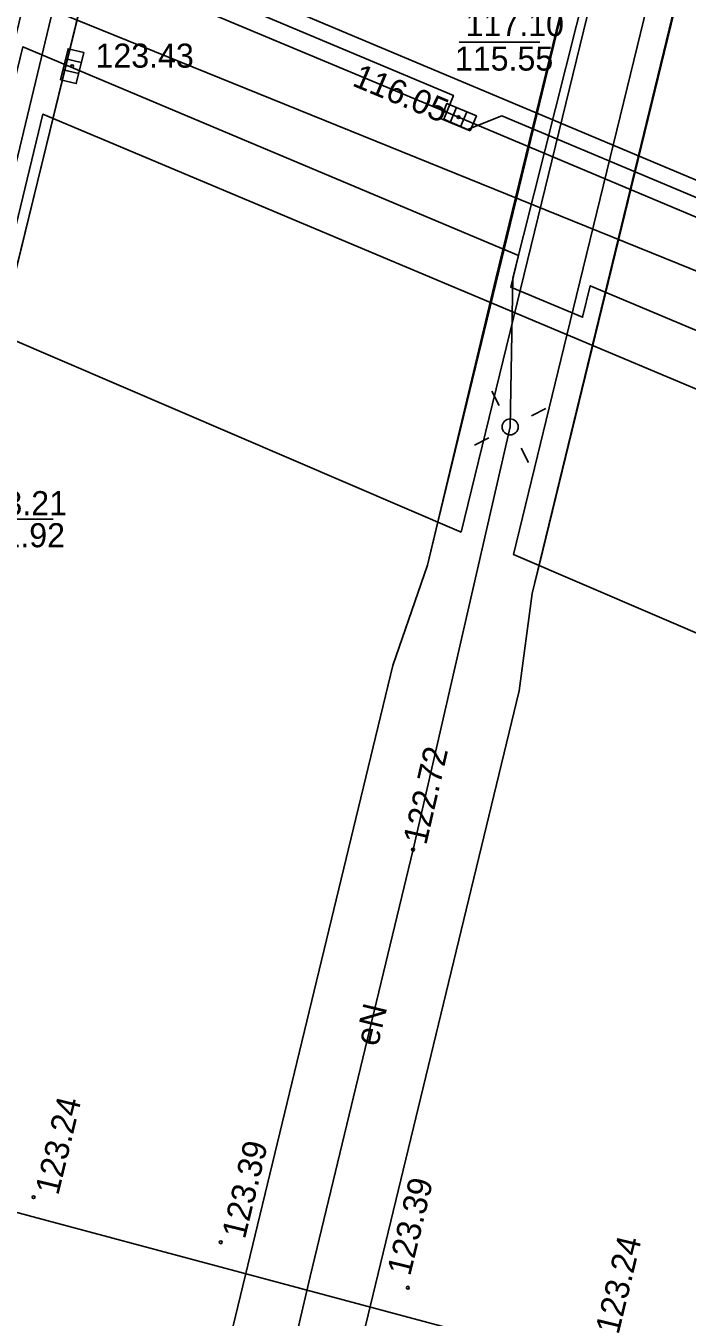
# Model space of a CAD drawing. Extents: x 6424617 to 6425697, y 5665845 to 5667190.
# Drawn here: x 6425440.97 to 6425461.6, y 5666910.57 to 5666950.84 of the extents above; entities that cross this region are included whole.
import ezdxf

# ---------------------------------------------------------------- set-up
doc = ezdxf.new("R2010")
doc.units = 0
for name, color, linetype in [('Warstwa 1', 7, 'Continuous'), ('Warstwa 12', 7, 'Continuous'), ('Warstwa 13', 7, 'Continuous'), ('Warstwa 14', 7, 'Continuous'), ('Warstwa 15', 7, 'Continuous'), ('Warstwa 16', 7, 'Continuous'), ('Warstwa 2', 7, 'Continuous'), ('Warstwa 25', 7, 'Continuous'), ('Warstwa 4', 7, 'Continuous'), ('Warstwa 6', 7, 'Continuous'), ('Warstwa 8', 7, 'Continuous')]:
    doc.layers.add(name, color=color, linetype=linetype)

msp = doc.modelspace()

# ---------------------------------------------------------------- linework, layer by layer
at = {"layer": 'Warstwa 1'}
msp.add_lwpolyline([(6425437.93, 5666938.04), (6425438.42, 5666937.92), (6425439.31, 5666941.59), (6425439.89, 5666941.44), (6425441.5, 5666948.08), (6425474.02, 5666934.4), (6425472.29, 5666927.24), (6425472.87, 5666927.1), (6425472.03, 5666923.61), (6425472.52, 5666923.49), (6425475.45, 5666935.64), (6425458.58, 5666942.73), (6425458.34, 5666941.75), (6425456.1, 5666942.69), (6425456.34, 5666943.68), (6425440.88, 5666950.18)], close=True, dxfattribs=at)
at = {"layer": 'Warstwa 12'}
for points in [[(6425431.89, 5666906.96), (6425430.9, 5666907.63), (6425434.54, 5666922.46), (6425436.49, 5666936.39), (6425438.5, 5666937.81), (6425438.62, 5666938.07), (6425450.24, 5666986.45), (6425451.95, 5666997.19), (6425461.13, 5667029.36), (6425461.175, 5667029.564)], [(6425478.115, 5667025.766), (6425475.61, 5667015.97), (6425473.13, 5667006.27), (6425470.44, 5666995.85), (6425469.89, 5666992.07), (6425464.59, 5666972.23), (6425464.47, 5666972.04), (6425462.8, 5666969.31), (6425456.16, 5666942.98), (6425456.08, 5666938.33), (6425453.05, 5666925.15), (6425449.84, 5666911.84), (6425448.16, 5666904.63), (6425448.88, 5666902.64)], [(6425464.654, 5666907.42), (6425437.078, 5666914.799), (6425417.814, 5666920.177), (6425402.666, 5666949.76), (6425401.834, 5666950.142), (6425366.69, 5666933.829), (6425365.771, 5666933.887), (6425355.729, 5666952.491), (6425344.802, 5666971.496), (6425344.013, 5666972.39), (6425340.424, 5666977.922), (6425339.576, 5666978.999), (6425339.462, 5666979.144), (6425339.323, 5666979.308), (6425317.451, 5667007.184), (6425317.021, 5667007.709), (6425316.481, 5667008.227), (6425313.859, 5667009.022)], [(6425553.71, 5666947.2), (6425549.6, 5666948.95), (6425497.24, 5666962.99), (6425496.43, 5666962.29), (6425494.49, 5666954.59), (6425489.02, 5666931.76), (6425484.64, 5666933.61), (6425476.81, 5666937.15), (6425438.84, 5666952.53), (6425435.57, 5666952.21), (6425429.97, 5666954.78), (6425402.11, 5666966.81), (6425387.27, 5666972.4), (6425380.77, 5666966.54), (6425363.64, 5666950.72), (6425363.13, 5666950.36), (6425362.37, 5666949.84), (6425357.72, 5666956.9), (6425346.14, 5666972.82)], [(6425429.54, 5666958.45), (6425436.02, 5666955.7), (6425454.47, 5666947.99), (6425472.9, 5666940.24)]]:
    msp.add_lwpolyline(points, dxfattribs=at)
at = {"layer": 'Warstwa 14'}
for p, q in [((6425457.007, 5666950.329), (6425454.489, 5666950.329)), ((6425441.823, 5666935.454), (6425439.227, 5666935.454))]:
    msp.add_line(p, q, dxfattribs=at)
for centre in [(6425442.42, 5666949.58), (6425454.009, 5666948.183), (6425454.47, 5666947.99), (6425453.05, 5666925.15)]:
    msp.add_circle(centre, 0.045, dxfattribs=at)
at = {"layer": 'Warstwa 16'}
for points in [[(6425454.547, 5666935.052), (6425462.72, 5666968.52), (6425464.269, 5666974.864), (6425448.68, 5666983.24), (6425443.29, 5666961.38), (6425438.561, 5666941.912)], [(6425473.666, 5666926.849), (6425456.184, 5666934.35), (6425458.05, 5666942), (6425464.35, 5666967.83), (6425465.856, 5666974.004), (6425483.16, 5666964.87)]]:
    msp.add_lwpolyline(points, close=True, dxfattribs=at)
at = {"layer": 'Warstwa 2'}
msp.add_circle((6425456.08, 5666938.33), 0.25, dxfattribs=at)
at = {"layer": 'Warstwa 25'}
for centre in [(6425441.216, 5666914.31), (6425447.052, 5666912.904), (6425452.889, 5666911.488)]:
    msp.add_circle(centre, 0.045, dxfattribs=at)
at = {"layer": 'Warstwa 4'}
for p, q in [((6425442.136, 5666949.468), (6425442.622, 5666949.352)), ((6425442.218, 5666949.808), (6425442.704, 5666949.692)), ((6425454.213, 5666947.826), (6425454.404, 5666948.288)), ((6425454.536, 5666947.692), (6425454.727, 5666948.154))]:
    msp.add_line(p, q, dxfattribs=at)
for points in [[(6425442.06, 5666949.152), (6425442.293, 5666950.124), (6425442.78, 5666950.008), (6425442.547, 5666949.036)], [(6425454.836, 5666947.568), (6425453.912, 5666947.95), (6425454.104, 5666948.412), (6425455.028, 5666948.03)]]:
    msp.add_lwpolyline(points, close=True, dxfattribs=at)
for points in [[(6425455.737, 5666938.997), (6425455.509, 5666939.442)], [(6425456.747, 5666938.673), (6425457.192, 5666938.901)], [(6425455.413, 5666937.987), (6425454.968, 5666937.759)], [(6425456.423, 5666937.663), (6425456.651, 5666937.218)]]:
    msp.add_lwpolyline(points, dxfattribs=at)
at = {"layer": 'Warstwa 6'}
for points in [[(6425436.9, 5666928.04), (6425438.55, 5666934.58), (6425438.01, 5666935.07), (6425438.19, 5666935.65), (6425438.86, 5666935.85), (6425442, 5666948.71), (6425445.18, 5666961.75), (6425451.11, 5666985.73), (6425451.49, 5666987.26), (6425450.84, 5666987.81), (6425450.92, 5666988.4), (6425451.78, 5666988.57), (6425453.11, 5666993.93)], [(6425472.746, 5666940.92), (6425455.819, 5666948.027), (6425454.751, 5666947.607), (6425454.007, 5666947.93), (6425454.31, 5666948.665), (6425437.423, 5666955.762), (6425436.224, 5666955.294), (6425435.539, 5666955.596), (6425434.673, 5666956.922), (6425418.113, 5666963.863), (6425417.778, 5666963.039), (6425417.044, 5666963.373), (6425416.197, 5666964.658), (6425399.757, 5666971.617), (6425399.412, 5666970.803), (6425398.678, 5666971.127), (6425397.821, 5666972.433), (6425378.826, 5666980.818), (6425379.045, 5666981.274)], [(6425453.5, 5666934.02), (6425455.63, 5666942.96), (6425462, 5666969.05), (6425464.07, 5666977.52)], [(6425467.43, 5666976.75), (6425465.18, 5666967.73), (6425462.01, 5666954.72), (6425458.83, 5666941.66), (6425456.77, 5666933.14)]]:
    msp.add_lwpolyline(points, dxfattribs=at)
at = {"layer": 'Warstwa 8'}
for p, q in [((6425440.171, 5666941.221), (6425450.281, 5666982.38)), ((6425453.82, 5666935.364), (6425463.519, 5666975.267)), ((6425456.98, 5666934.008), (6425466.642, 5666973.589)), ((6425401.285, 5666971.5), (6425496.325, 5666931.551)), ((6425453.5, 5666934.02), (6425453.82, 5666935.364)), ((6425452.419, 5666930.893), (6425453.5, 5666934.02)), ((6425456.77, 5666933.14), (6425456.98, 5666934.008)), ((6425456.356, 5666930.102), (6425456.77, 5666933.14)), ((6425423.991, 5666813.287), (6425452.419, 5666930.893)), ((6425428.098, 5666813.237), (6425456.356, 5666930.102))]:
    msp.add_line(p, q, dxfattribs=at)

# ---------------------------------------------------------------- texts
at = {"layer": 'Warstwa 13'}
msp.add_text('eN', height=0.75, rotation=76.4383, dxfattribs=at).set_placement((6425451.949, 5666918.986))
at = {"layer": 'Warstwa 14'}
for s, p in [('115.55', (6425454.356, 5666949.442)), ('121.92', (6425439.128, 5666934.578))]:
    msp.add_text(s, height=0.75, dxfattribs=at).set_placement(p)
for s, rotation, p in [('116.05', 337.3232, (6425451.119, 5666948.984)), ('122.72', 77.0514, (6425453.461, 5666925.265))]:
    msp.add_text(s, height=0.75, rotation=rotation, dxfattribs=at).set_placement(p)
at = {"layer": 'Warstwa 15'}
for s, p in [('117.10', (6425454.69, 5666950.516)), ('123.43', (6425443.146, 5666949.533)), ('123.21', (6425439.19, 5666935.578))]:
    msp.add_text(s, height=0.75, dxfattribs=at).set_placement(p)
at = {"layer": 'Warstwa 25'}
for s, rotation, p in [('123.24', 76.4097, (6425441.984, 5666914.346)), ('123.39', 76.4097, (6425447.806, 5666912.979)), ('123.39', 76.4039, (6425452.959, 5666911.826)), ('123.24', 76.4039, (6425459.458, 5666910.003))]:
    msp.add_text(s, height=0.75, rotation=rotation, dxfattribs=at).set_placement(p)

doc.saveas('drawing.dxf')
